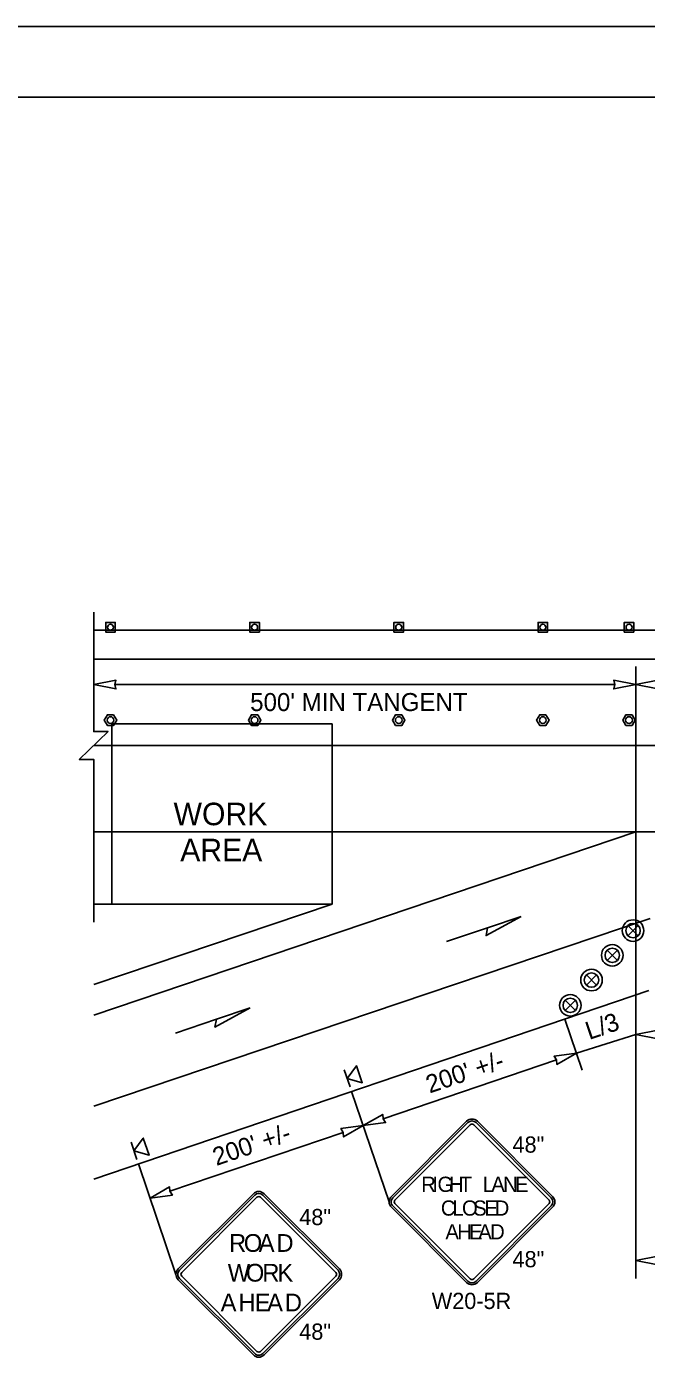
# Model space of a CAD drawing. Extents: x 99999 to 100116, y 99995 to 100013.
# Drawn here: x 100047.9 to 100050.65, y 100004.77 to 100010.69 of the extents above; entities that cross this region are included whole.
import ezdxf

# ---------------------------------------------------------------- set-up
doc = ezdxf.new("R2010")
doc.units = 0
for name, color, linetype in [('RD_MK_LineEdgeYellow', 7, 'Continuous'), ('RD_MK_LineLane', 7, 'Continuous'), ('SH_GI_PlotLimits', 7, 'Continuous'), ('SH_GI_SheetBorder', 7, 'Continuous'), ('TR_SN_ConstructionSigns', 7, 'Continuous'), ('TR_WZ_PortableSignMountBlk-Org', 7, 'Continuous'), ('TR_WZ_TallChanDevice', 7, 'Continuous'), ('TR_WZ_TrafficCone', 7, 'Continuous'), ('TR_WZ_TrafficSafetyDrum', 7, 'Continuous'), ('TR_WZ_WorkAreaLabel', 7, 'Continuous'), ('TR_WZ_WorkZoneDetails', 7, 'Continuous'), ('TR_WZ_WorkZoneTextCurrent', 7, 'Continuous')]:
    doc.layers.add(name, color=color, linetype=linetype)

msp = doc.modelspace()

# ---------------------------------------------------------------- linework, layer by layer
at = {"layer": 'RD_MK_LineEdgeYellow'}
for p, q in [((100048.195, 100007.8789), (100055.43, 100007.8789)), ((100048.195, 100007.1109), (100049.2533, 100007.1109)), ((100050.6655, 100006.7269), (100048.195, 100005.8927)), ((100049.2943, 100006.6692), (100048.195, 100006.298))]:
    msp.add_line(p, q, dxfattribs=at)
at = {"layer": 'RD_MK_LineLane'}
for points in [[(100055.43, 100007.4949), (100048.195, 100007.4949)], [(100052.1758, 100007.1109), (100050.6024, 100007.1109)], [(100052.1758, 100007.1109), (100050.6024, 100007.1109)]]:
    msp.add_lwpolyline(points, dxfattribs=at)
at = {"layer": 'SH_GI_PlotLimits'}
msp.add_lwpolyline([(100039.0625, 99999.6875), (100056.0625, 99999.6875), (100056.0625, 100010.6875), (100039.0625, 100010.6875)], close=True, dxfattribs=at)
at = {"layer": 'SH_GI_SheetBorder'}
msp.add_line((100040, 100010.375), (100055.75, 100010.375), dxfattribs=at)
at = {"layer": 'TR_SN_ConstructionSigns'}
for p, q in [((100049.8509, 100005.8261), (100049.5168, 100005.492)), ((100050.2327, 100005.492), (100049.8986, 100005.8261)), ((100049.8568, 100005.8202), (100049.5227, 100005.4861)), ((100049.5327, 100005.4761), (100049.8668, 100005.8102)), ((100049.8827, 100005.8102), (100050.2168, 100005.4761)), ((100050.2267, 100005.4861), (100049.8926, 100005.8202)), ((100048.9041, 100005.5043), (100048.57, 100005.1702)), ((100048.91, 100005.4983), (100048.5759, 100005.1642)), ((100048.5859, 100005.1543), (100048.92, 100005.4884)), ((100048.9359, 100005.4884), (100049.27, 100005.1543)), ((100049.28, 100005.1642), (100048.9458, 100005.4983)), ((100049.2859, 100005.1702), (100048.9518, 100005.5043)), ((100049.5168, 100005.4443), (100049.8509, 100005.1102)), ((100049.5227, 100005.4503), (100049.8568, 100005.1162)), ((100049.8668, 100005.1261), (100049.5327, 100005.4602)), ((100050.2168, 100005.4602), (100049.8827, 100005.1261)), ((100049.8926, 100005.1162), (100050.2267, 100005.4503)), ((100049.8986, 100005.1102), (100050.2327, 100005.4443)), ((100048.57, 100005.1224), (100048.9041, 100004.7883)), ((100048.5759, 100005.1284), (100048.91, 100004.7943)), ((100048.92, 100004.8043), (100048.5859, 100005.1384)), ((100049.27, 100005.1384), (100048.9359, 100004.8043)), ((100048.9458, 100004.7943), (100049.28, 100005.1284)), ((100048.9518, 100004.7883), (100049.2859, 100005.1224))]:
    msp.add_line(p, q, dxfattribs=at)
for centre, radius, start, end in [((100049.8747, 100005.8023), 0.0338, 45, 135), ((100049.8747, 100005.8023), 0.0253, 45, 135), ((100049.8747, 100005.8023), 0.0113, 45, 135), ((100048.9279, 100005.4804), 0.0338, 45, 135), ((100048.9279, 100005.4804), 0.0253, 45, 135), ((100048.9279, 100005.4804), 0.0113, 45, 135), ((100049.5406, 100005.4682), 0.0338, 135, 225.00001), ((100049.5406, 100005.4682), 0.0253, 135, 225.00001), ((100049.5406, 100005.4682), 0.0113, 135, 225.00001), ((100050.2088, 100005.4682), 0.0113, 315.00002, 45), ((100050.2088, 100005.4682), 0.0253, 315.00002, 45), ((100050.2088, 100005.4682), 0.0338, 315.00001, 45.00001), ((100048.5938, 100005.1463), 0.0338, 135, 225.00001), ((100048.5938, 100005.1463), 0.0253, 135, 225.00001), ((100048.5938, 100005.1463), 0.0113, 135, 225.00001), ((100049.2621, 100005.1463), 0.0113, 315.00002, 45), ((100049.2621, 100005.1463), 0.0253, 315.00002, 45), ((100049.2621, 100005.1463), 0.0338, 315.00001, 45.00001), ((100049.8747, 100005.1341), 0.0253, 225.00001, 315.00002), ((100049.8747, 100005.1341), 0.0113, 225.00001, 315.00002), ((100049.8747, 100005.1341), 0.0338, 225.00001, 315.00001), ((100048.9279, 100004.8122), 0.0338, 225.00001, 315.00001), ((100048.9279, 100004.8122), 0.0253, 225.00001, 315.00002), ((100048.9279, 100004.8122), 0.0113, 225.00001, 315.00002)]:
    msp.add_arc(centre, radius, start, end, dxfattribs=at)
at = {"layer": 'TR_WZ_PortableSignMountBlk-Org'}
for p, q in [((100049.3333, 100005.9787), (100049.3076, 100006.0545)), ((100048.3865, 100005.6569), (100048.3608, 100005.7326))]:
    msp.add_line(p, q, dxfattribs=at)
for points in [[(100049.3205, 100006.0165), (100049.362, 100006.0729), (100049.3877, 100005.9972)], [(100048.3737, 100005.6947), (100048.4152, 100005.7511), (100048.4409, 100005.6753)]]:
    msp.add_lwpolyline(points, close=True, dxfattribs=at)
at = {"layer": 'TR_WZ_TallChanDevice'}
for points in [[(100048.2833, 100007.6319), (100048.2555, 100007.6319), (100048.2417, 100007.6079), (100048.2555, 100007.5839), (100048.2833, 100007.5839), (100048.2971, 100007.6079)], [(100048.9233, 100007.6319), (100048.8955, 100007.6319), (100048.8817, 100007.6079), (100048.8955, 100007.5839), (100048.9233, 100007.5839), (100048.9371, 100007.6079)], [(100049.5633, 100007.6319), (100049.5355, 100007.6319), (100049.5217, 100007.6079), (100049.5355, 100007.5839), (100049.5633, 100007.5839), (100049.5771, 100007.6079)], [(100050.2033, 100007.6319), (100050.1755, 100007.6319), (100050.1617, 100007.6079), (100050.1755, 100007.5839), (100050.2033, 100007.5839), (100050.2171, 100007.6079)], [(100050.5859, 100007.6319), (100050.5582, 100007.6319), (100050.5443, 100007.6079), (100050.5582, 100007.5839), (100050.5859, 100007.5839), (100050.5997, 100007.6079)]]:
    msp.add_lwpolyline(points, close=True, dxfattribs=at)
for points in [[(100048.2833, 100007.6319), (100048.2555, 100007.6319), (100048.2417, 100007.6079), (100048.2555, 100007.5839), (100048.2833, 100007.5839), (100048.2971, 100007.6079), (100048.2833, 100007.6319)], [(100048.9233, 100007.6319), (100048.8955, 100007.6319), (100048.8817, 100007.6079), (100048.8955, 100007.5839), (100048.9233, 100007.5839), (100048.9371, 100007.6079), (100048.9233, 100007.6319)], [(100049.5633, 100007.6319), (100049.5355, 100007.6319), (100049.5217, 100007.6079), (100049.5355, 100007.5839), (100049.5633, 100007.5839), (100049.5771, 100007.6079), (100049.5633, 100007.6319)], [(100050.2033, 100007.6319), (100050.1755, 100007.6319), (100050.1617, 100007.6079), (100050.1755, 100007.5839), (100050.2033, 100007.5839), (100050.2171, 100007.6079), (100050.2033, 100007.6319)], [(100050.5859, 100007.6319), (100050.5582, 100007.6319), (100050.5443, 100007.6079), (100050.5582, 100007.5839), (100050.5859, 100007.5839), (100050.5997, 100007.6079), (100050.5859, 100007.6319)]]:
    msp.add_lwpolyline(points, dxfattribs=at)
for centre in [(100048.2694, 100007.6079), (100048.9094, 100007.6079), (100049.5494, 100007.6079), (100050.1894, 100007.6079), (100050.572, 100007.6079)]:
    msp.add_circle(centre, 0.015, dxfattribs=at)
at = {"layer": 'TR_WZ_TrafficCone'}
for points in [[(100048.2481, 100008.0416), (100048.2907, 100008.0416), (100048.2907, 100007.9989), (100048.2481, 100007.9989), (100048.2481, 100008.0416)], [(100048.2481, 100007.9989), (100048.2907, 100007.9989), (100048.2907, 100008.0416), (100048.2481, 100008.0416), (100048.2481, 100007.9989)], [(100048.8881, 100008.0416), (100048.9307, 100008.0416), (100048.9307, 100007.9989), (100048.8881, 100007.9989), (100048.8881, 100008.0416)], [(100048.8881, 100007.9989), (100048.9307, 100007.9989), (100048.9307, 100008.0416), (100048.8881, 100008.0416), (100048.8881, 100007.9989)], [(100049.5281, 100008.0416), (100049.5707, 100008.0416), (100049.5707, 100007.9989), (100049.5281, 100007.9989), (100049.5281, 100008.0416)], [(100049.5281, 100007.9989), (100049.5707, 100007.9989), (100049.5707, 100008.0416), (100049.5281, 100008.0416), (100049.5281, 100007.9989)], [(100050.1681, 100008.0416), (100050.2107, 100008.0416), (100050.2107, 100007.9989), (100050.1681, 100007.9989), (100050.1681, 100008.0416)], [(100050.1681, 100007.9989), (100050.2107, 100007.9989), (100050.2107, 100008.0416), (100050.1681, 100008.0416), (100050.1681, 100007.9989)], [(100050.5507, 100008.0416), (100050.5934, 100008.0416), (100050.5934, 100007.9989), (100050.5507, 100007.9989), (100050.5507, 100008.0416)], [(100050.5507, 100007.9989), (100050.5934, 100007.9989), (100050.5934, 100008.0416), (100050.5507, 100008.0416), (100050.5507, 100007.9989)]]:
    msp.add_lwpolyline(points, dxfattribs=at)
for centre in [(100048.2694, 100008.0202), (100048.9094, 100008.0202), (100049.5494, 100008.0202), (100050.1894, 100008.0202), (100050.572, 100008.0202)]:
    msp.add_circle(centre, 0.0133, dxfattribs=at)
at = {"layer": 'TR_WZ_TrafficSafetyDrum'}
for p, q in [((100050.5673, 100006.6956), (100050.6125, 100006.6503)), ((100050.6125, 100006.6956), (100050.5673, 100006.6503)), ((100050.4751, 100006.5857), (100050.5203, 100006.5404)), ((100050.5203, 100006.5857), (100050.4751, 100006.5404)), ((100050.3829, 100006.4758), (100050.4281, 100006.4306)), ((100050.4281, 100006.4758), (100050.3829, 100006.4306)), ((100050.2886, 100006.3636), (100050.3339, 100006.3183)), ((100050.3339, 100006.3636), (100050.2886, 100006.3183))]:
    msp.add_line(p, q, dxfattribs=at)
for centre, radius in [((100050.5899, 100006.6729), 0.048), ((100050.5899, 100006.6729), 0.048), ((100050.5899, 100006.6729), 0.032), ((100050.4977, 100006.5631), 0.048), ((100050.4977, 100006.5631), 0.048), ((100050.4977, 100006.5631), 0.032), ((100050.4055, 100006.4532), 0.048), ((100050.4055, 100006.4532), 0.048), ((100050.4055, 100006.4532), 0.032), ((100050.3113, 100006.3409), 0.048), ((100050.3113, 100006.3409), 0.048), ((100050.3113, 100006.3409), 0.032)]:
    msp.add_circle(centre, radius, dxfattribs=at)
at = {"layer": 'TR_WZ_WorkZoneDetails'}
for p, q in [((100048.195, 100008.0069), (100055.43, 100008.0069)), ((100050.6024, 100007.8459), (100050.6024, 100005.1282)), ((100050.5087, 100007.7659), (100048.2887, 100007.7659)), ((100049.2533, 100007.1109), (100050.6024, 100007.1109)), ((100050.6024, 100007.1109), (100049.2943, 100006.6692)), ((100048.195, 100006.7909), (100049.2533, 100006.7909)), ((100049.2533, 100006.7909), (100048.195, 100006.4338)), ((100049.9441, 100006.6859), (100049.7613, 100006.6242)), ((100048.195, 100005.5689), (100050.6601, 100006.4069)), ((100048.7404, 100006.2795), (100048.5576, 100006.2178)), ((100050.2871, 100006.2801), (100050.3643, 100006.0529)), ((100050.6024, 100006.2119), (100050.3386, 100006.1286)), ((100050.2498, 100006.0985), (100049.4805, 100005.8369)), ((100049.3403, 100005.9583), (100049.5069, 100005.4682)), ((100049.303, 100005.7766), (100048.5337, 100005.5151)), ((100048.3935, 100005.6364), (100048.5601, 100005.1463))]:
    msp.add_line(p, q, dxfattribs=at)
msp.add_lwpolyline([(100048.195, 100006.7109), (100048.195, 100007.433), (100048.131, 100007.433), (100048.259, 100007.5569), (100048.195, 100007.5569), (100048.195, 100008.0869)], dxfattribs=at)
for points in [[(100048.195, 100007.7659), (100048.2933, 100007.7851), (100048.2887, 100007.7659), (100048.2933, 100007.7466)], [(100050.6024, 100007.7659), (100050.5041, 100007.7851), (100050.5087, 100007.7659), (100050.5041, 100007.7466)], [(100050.6024, 100007.7659), (100050.7007, 100007.7851), (100050.6962, 100007.7659), (100050.7007, 100007.7466)], [(100048.275, 100006.7909), (100048.275, 100007.5909), (100049.2533, 100007.5909), (100049.2533, 100006.7909)], [(100050.093, 100006.7362), (100049.9371, 100006.651), (100049.9441, 100006.6859)], [(100048.8893, 100006.3298), (100048.7333, 100006.2445), (100048.7404, 100006.2795)], [(100050.6024, 100006.2119), (100050.7007, 100006.2312), (100050.6962, 100006.2119), (100050.7007, 100006.1926)], [(100050.3386, 100006.1286), (100050.2393, 100006.1152), (100050.2498, 100006.0985), (100050.2517, 100006.0787)], [(100049.3918, 100005.8068), (100049.4786, 100005.8567), (100049.4805, 100005.8369), (100049.491, 100005.8202)], [(100049.3918, 100005.8068), (100049.2925, 100005.7934), (100049.303, 100005.7766), (100049.3049, 100005.7569)], [(100048.445, 100005.4849), (100048.5318, 100005.5348), (100048.5337, 100005.5151), (100048.5442, 100005.4983)], [(100050.6024, 100005.2082), (100050.7007, 100005.2275), (100050.6962, 100005.2082), (100050.7007, 100005.1889)]]:
    msp.add_lwpolyline(points, close=True, dxfattribs=at)

# ---------------------------------------------------------------- texts
at = {"layer": 'TR_SN_ConstructionSigns'}
for s, height, p in [('48"', 0.072, (100050.0545, 100005.6867)), ('R', 0.0675, (100049.6493, 100005.5125)), ('I', 0.0675, (100049.6986, 100005.5125)), ('G', 0.0675, (100049.7215, 100005.5125)), ('H', 0.0675, (100049.7728, 100005.5125)), ('T', 0.0675, (100049.8201, 100005.5125)), ('L', 0.0675, (100049.922, 100005.5125)), ('A', 0.0675, (100049.9605, 100005.5125)), ('N', 0.0675, (100050.0131, 100005.5125)), ('E', 0.0675, (100050.0658, 100005.5125)), ('C', 0.0675, (100049.7364, 100005.407)), ('L', 0.0675, (100049.7877, 100005.407)), ('O', 0.0675, (100049.8302, 100005.407)), ('S', 0.0675, (100049.8801, 100005.407)), ('E', 0.0675, (100049.9294, 100005.407)), ('D', 0.0675, (100049.9753, 100005.407)), ('48"', 0.072, (100049.1077, 100005.3649)), ('A', 0.0675, (100049.7566, 100005.3015)), ('H', 0.0675, (100049.8093, 100005.3015)), ('E', 0.0675, (100049.8619, 100005.3015)), ('A', 0.0675, (100049.9024, 100005.3015)), ('D', 0.0675, (100049.9551, 100005.3015)), ('R', 0.0788, (100048.796, 100005.2462)), ('O', 0.0788, (100048.8614, 100005.2462)), ('A', 0.0788, (100048.9276, 100005.2462)), ('D', 0.0788, (100049.0063, 100005.2462)), ('48"', 0.072, (100050.0545, 100005.1776)), ('W', 0.0788, (100048.7901, 100005.114)), ('O', 0.0788, (100048.8705, 100005.114)), ('R', 0.0788, (100048.9437, 100005.114)), ('K', 0.0788, (100049.0106, 100005.114)), ('A', 0.0788, (100048.7586, 100004.9818)), ('H', 0.0788, (100048.8374, 100004.9818)), ('E', 0.0788, (100048.9098, 100004.9818)), ('A', 0.0788, (100048.965, 100004.9818)), ('D', 0.0788, (100049.0437, 100004.9818)), ('W20-5R', 0.072, (100049.6961, 100004.9923)), ('48"', 0.072, (100049.1077, 100004.8558))]:
    msp.add_text(s, height=height, rotation=360, dxfattribs=at).set_placement(p)
at = {"layer": 'TR_WZ_WorkAreaLabel'}
for s, p in [('WORK', (100048.5496, 100007.1409)), ('AREA', (100048.5793, 100006.9809))]:
    msp.add_text(s, height=0.1, dxfattribs=at).set_placement(p)
at = {"layer": 'TR_WZ_WorkZoneTextCurrent'}
msp.add_text("500' MIN TANGENT", height=0.08, dxfattribs=at).set_placement((100048.8897, 100007.6479))
for s, p in [('L/3', (100050.3951, 100006.1869)), ("200' +/-", (100049.6866, 100005.9492)), ("200' +/-", (100048.7398, 100005.6274))]:
    msp.add_text(s, height=0.08, rotation=18.77496, dxfattribs=at).set_placement(p)

doc.saveas('drawing.dxf')
